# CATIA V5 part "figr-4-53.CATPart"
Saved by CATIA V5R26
Part number: Part1
Material "Aluminium": density 2710 kg/m3, Young's modulus 7e+10 Pa, Poisson ratio 0.346, thermal expansion 2.36e-05 1/K
Bounding box of the stored display mesh (mm): x -69.981 to 69.981, y -240 to 0, z -69.908 to 69.908
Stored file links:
  D:\_Deepak\CATIA\CATIA V5-6R2016_Deepak\Resources\Part files\Partfiles\c04_catia_v5_6r2016_prt\figr-4-53.CATPart
  C:\Program Files\Dassault Systemes\B26\win_b64\startup\materials\Catalog.CATMaterial
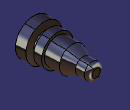
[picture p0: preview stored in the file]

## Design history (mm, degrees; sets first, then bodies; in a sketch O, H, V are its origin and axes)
Body1 (main body), material "Steel"
  Sketch1 on yz-plane, origin (0, 0, 0), H (0, 1, 0), V (0, 0, 1)
    line L1 (0, 0) -> (0, 15.359)
    arc A1 centre (-15.359, 15.359) radius 15.359 from (0, 15.359) to (-15.359, 30.718) ccw
    point P2 (-15.359, 15.359)
    line L2 (-15.359, 30.718) -> (-49.6877, 30.718)
    line L3 (-49.6877, 30.718) -> (-91.8922, 49.6007)
    line L4 (-91.8922, 49.6007) -> (-149.3038, 49.6007)
    line L5 (-149.3038, 49.6007) -> (-149.3038, 60)
    line L6 (-149.3038, 60) -> (-180, 60)
    line L7 (-180, 60) -> (-180, 38.9967)
    line L8 (-180, 38.9967) -> (-200, 40)
    line L9 (-200, 40) -> (-200, 70)
    line L10 (-200, 70) -> (-240, 70)
    line L11 (-240, 70) -> (-240, 0)
    line L12 (-240, 0) -> (0, 0)
    axis line L13 (-300, 0) -> (50, 0)
    vertical: L1 V, L5 V, L7 V, L9 V, L11 V
    tangency: A1 L1, L2 A1, L8 A1, L12 A1, L13 A1
    coincidence: L3 P2
    horizontal: L4 H, L6 H, L10 H, L2 H
    fix: L12
  Shaft1: profile Sketch1, axis Sketch1.H, angle 360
